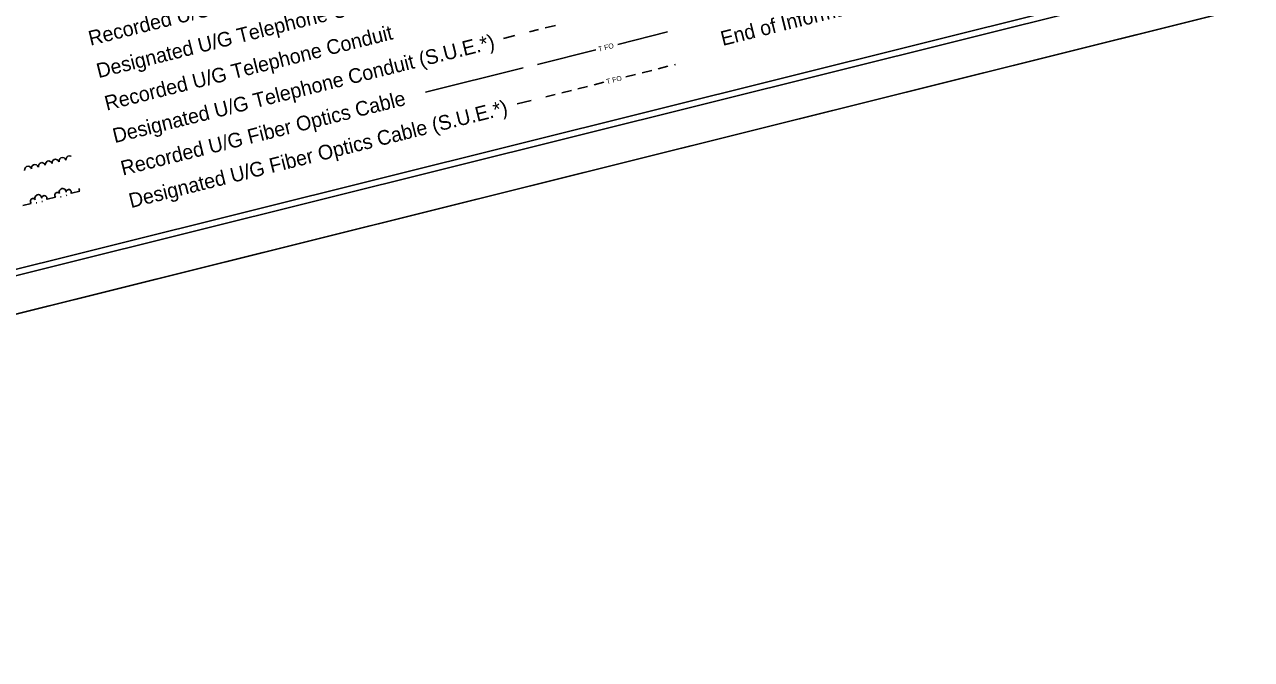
# Model space of a CAD drawing. Extents: x 1030323 to 1034123, y 654802 to 657751.
# Drawn here: x 1031688 to 1032422, y 654802 to 655181 of the extents above; entities that cross this region are included whole.
import ezdxf

# ---------------------------------------------------------------- set-up
doc = ezdxf.new("R2010")
doc.units = 0
for name, color, linetype in [('Sheet Cutting Line CELL', 7, 'Continuous'), ('Sheet Plot Border Inside CELL', 7, 'Continuous'), ('Sheet Plot Border Outside CELL', 7, 'Continuous'), ('Sheet Symbology CELL', 7, 'Continuous')]:
    doc.layers.add(name, color=color, linetype=linetype)

msp = doc.modelspace()

# ---------------------------------------------------------------- linework, layer by layer
at = {"layer": 'Sheet Cutting Line CELL'}
msp.add_line((1030855.21, 654801.72), (1032489.19, 655209.12), dxfattribs=at)
at = {"layer": 'Sheet Plot Border Inside CELL'}
msp.add_lwpolyline([(1030862.39, 654826.65), (1032479.39, 655229.81), (1032224.14, 656253.57), (1030607.14, 655850.41)], close=True, dxfattribs=at)
at = {"layer": 'Sheet Plot Border Outside CELL'}
msp.add_lwpolyline([(1030855.21, 654801.72), (1032489.19, 655209.12), (1032223.08, 656276.44), (1030589.1, 655869.05)], close=True, dxfattribs=at)
at = {"layer": 'Sheet Symbology CELL'}
for p, q in [((1031999.32, 655179.03), (1032005.62, 655180.61)), ((1031981.27, 655174.53), (1031974.42, 655172.82)), ((1031990.01, 655176.71), (1031995.44, 655178.07)), ((1032042.76, 655169.25), (1032072.48, 655176.66)), ((1031994.85, 655157.31), (1032029.66, 655165.99)), ((1032076.67, 655157.1), (1032077.31, 655157.26)), ((1031986.11, 655155.13), (1031927.87, 655140.61)), ((1032047.56, 655149.84), (1032053.38, 655151.29)), ((1032057.27, 655152.26), (1032063.09, 655153.71)), ((1032066.97, 655154.68), (1032072.79, 655156.13)), ((1032018.94, 655142.7), (1032024.76, 655144.15)), ((1032028.64, 655145.12), (1032034.46, 655146.57)), ((1031990.95, 655135.72), (1031982.64, 655133.65)), ((1031999.69, 655137.9), (1032005.36, 655139.31)), ((1032009.24, 655140.28), (1032015.06, 655141.73)), ((1031697.51, 655098.35), (1031698.43, 655098.58)), ((1031698.43, 655098.58), (1031699.33, 655098.29)), ((1031700.54, 655097.97), (1031700.97, 655098.75)), ((1031700.97, 655098.75), (1031701.64, 655099.38)), ((1031701.64, 655099.38), (1031702.56, 655099.61)), ((1031702.56, 655099.61), (1031703.46, 655099.32)), ((1031703.46, 655099.32), (1031704.15, 655098.82)), ((1031704.15, 655098.82), (1031704.55, 655098.04)), ((1031704.61, 655098.01), (1031704.67, 655099)), ((1031704.67, 655099), (1031705.09, 655099.78)), ((1031705.09, 655099.78), (1031705.76, 655100.41)), ((1031705.76, 655100.41), (1031706.68, 655100.64)), ((1031706.68, 655100.64), (1031707.58, 655100.35)), ((1031707.58, 655100.35), (1031708.27, 655099.85)), ((1031708.27, 655099.85), (1031708.67, 655099.07)), ((1031708.73, 655099.04), (1031708.79, 655100.03)), ((1031708.79, 655100.03), (1031709.22, 655100.81)), ((1031709.22, 655100.81), (1031709.88, 655101.44)), ((1031709.88, 655101.44), (1031710.81, 655101.67)), ((1031710.81, 655101.67), (1031711.7, 655101.38)), ((1031711.7, 655101.38), (1031712.39, 655100.88)), ((1031712.39, 655100.88), (1031712.79, 655100.1)), ((1031712.85, 655100.06), (1031712.92, 655101.06)), ((1031712.92, 655101.06), (1031713.34, 655101.83)), ((1031713.34, 655101.83), (1031714.01, 655102.47)), ((1031714.01, 655102.47), (1031714.93, 655102.69)), ((1031714.93, 655102.69), (1031715.83, 655102.4)), ((1031715.83, 655102.4), (1031715.89, 655102.37)), ((1031688.11, 655093.9), (1031688.17, 655094.89)), ((1031688.17, 655094.89), (1031688.6, 655095.67)), ((1031688.6, 655095.67), (1031689.26, 655096.3)), ((1031689.26, 655096.3), (1031690.19, 655096.53)), ((1031690.19, 655096.53), (1031691.08, 655096.23)), ((1031691.08, 655096.23), (1031691.77, 655095.74)), ((1031691.77, 655095.74), (1031692.17, 655094.96)), ((1031692.24, 655094.92), (1031692.3, 655095.92)), ((1031692.3, 655095.92), (1031692.72, 655096.69)), ((1031692.72, 655096.69), (1031693.39, 655097.32)), ((1031693.39, 655097.32), (1031694.31, 655097.55)), ((1031694.31, 655097.55), (1031695.21, 655097.26)), ((1031695.21, 655097.26), (1031695.9, 655096.76)), ((1031695.9, 655096.76), (1031696.3, 655095.99)), ((1031696.36, 655095.95), (1031696.42, 655096.95)), ((1031696.42, 655096.95), (1031696.85, 655097.72)), ((1031696.85, 655097.72), (1031697.51, 655098.35)), ((1031699.33, 655098.29), (1031700.02, 655097.79)), ((1031700.02, 655097.79), (1031700.42, 655097.02)), ((1031700.48, 655096.98), (1031700.54, 655097.97)), ((1031701.68, 655076.67), (1031706.53, 655077.88)), ((1031709.52, 655078.11), (1031710, 655078.23)), ((1031712.91, 655078.95), (1031713.4, 655079.07)), ((1031716.24, 655080.3), (1031721.09, 655081.51)), ((1031687.13, 655073.04), (1031691.98, 655074.25)), ((1031694.96, 655074.48), (1031695.45, 655074.6)), ((1031698.36, 655075.32), (1031698.84, 655075.44))]:
    msp.add_line(p, q, dxfattribs=at)
msp.add_lwpolyline([(1032212.63, 656248.07), (1030757.19, 655885.19), (1031010.96, 654867.37), (1032466.4, 655230.25)], close=True, dxfattribs=at)
for centre, radius, start, end in [((1031693.14, 655075.58), 1.58, 32.43495, 233.23152), ((1031696.29, 655077.4), 2.06, 359.96376, 208.03624), ((1031699.93, 655077.28), 1.58, 334.76848, 175.56505), ((1031707.69, 655079.21), 1.58, 32.43495, 233.23152), ((1031710.85, 655081.03), 2.06, 359.96376, 208.03624), ((1031714.48, 655080.91), 1.58, 334.76848, 175.56505), ((1031722.25, 655082.84), 1.58, 170.25102, 217.74899)]:
    msp.add_arc(centre, radius, start, end, dxfattribs=at)

# ---------------------------------------------------------------- texts
for s, height, p in [('Recorded U/G Telephone Cable', 8.75, (1031727.51, 655168.42)), ('Designated U/G Telephone Cable (S.U.E.*)', 8.75, (1031732.35, 655149.02)), ('End of Information', 8.75, (1032105.51, 655168.3)), ('Recorded U/G Telephone Conduit', 8.75, (1031737.19, 655129.61)), ('Designated U/G Telephone Conduit (S.U.E.*)', 8.75, (1031742.02, 655110.21)), ('T FO', 3, (1032031.48, 655164.89)), ('T FO', 3, (1032036.28, 655145.48)), ('Recorded U/G Fiber Optics Cable', 8.75, (1031746.86, 655090.8)), ('Designated U/G Fiber Optics Cable (S.U.E.*)', 8.75, (1031751.7, 655071.39))]:
    msp.add_text(s, height=height, rotation=14, dxfattribs=at).set_placement(p)

doc.saveas('drawing.dxf')
